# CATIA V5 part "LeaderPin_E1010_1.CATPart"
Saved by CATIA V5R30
Part number: Vodící čep_15-36/95
Nomenclature: E1010/15-36/95
Description: MEUSBURGER
Property "Material": "1.7131"
Publications: "DrillHole", "Base"
Bounding box of the stored display mesh (mm): x -12.298 to 12.298, y -12.297 to 12.297, z 0 to 131
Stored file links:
  E:\Bakalarka\Model\Forma_v7\LeaderPin_E1010_1.CATPart
  E:\dev\MoldDesign\intel_a\startup\components\MoldCatalog\LeaderPin\Meusburger\LeaderPin_E1010\TableE1010.txt
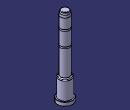
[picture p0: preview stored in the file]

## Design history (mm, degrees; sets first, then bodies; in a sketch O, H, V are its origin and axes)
Parameters
  Ref = "E1010/15-36/95" {design table}
  L1 = 36 mm {design table}
  L2 = 95 mm {design table}
  L3 = 6 mm {design table}
  L4 = 5 mm {design table}
  L5 = 25 mm {design table}
  L6 = 50 mm {design table}
  L7 = 0 mm {design table}
  L8 = 0 mm {design table}
  L11 = 2.4 mm {design table}
  L12 = 10 mm {design table}
  L13 = 2.5 mm {design table}
  D1 = 20 mm {design table}
  D2 = 15 mm {design table}
  D3 = 24.6 mm {design table}
  D4 = 14.6 mm {design table}
  D5 = 14.2 mm {design table}
  R = 1 mm {design table}
  R1 = 15 mm {design table}
  R3 = 1.8 mm {design table}
  R4 = 2 mm {design table}
  R5 = 1 mm {design table}
  F = 0.3 mm {design table}
  W = 15 deg {design table}
  X = 5.5 mm {design table}
  L0 = 131 mm {design table}
  k_d3 = 26 mm {design table}
  k_l3 = 6.3 mm {design table}
  Mat = "1.7131" {design table}
  HeatTreat = "60HRC" {design table}
  SupplierRef = "Meusburger 2017"
  BmpRef = "F_MldLeaderPin_D2_L"
  D = 15 mm {= D2}
  ThL = 36 mm {= L1}
  ThD = 24.6 mm {= D3}
  DrillHole_Length = 225 mm
  L = 95 mm {= L2}
Fillet1: radius 1.8 {= R3}, on edge [face of Shaft1 from Sketch1.L5 | face of Shaft1 from Sketch1.L4]
Set1 "BaseBody"
  Point1 "Base": (0, 0, 0)
  Plane1: type Offset, RefPlane xy-plane, Offset 225 {= DrillHole_Length}, reversed
Body1 "PartBody" (main body)
  Sketch1 on zx-plane, origin (0, 0, 0), H (1, 0, 0), V (0, 0, -1)
    point P1 (0, 0)
    line L1 (0, 0) -> (12.3, 0)
    line L2 (12.3, 0) -> (12.3, -6)
    line L3 (12.3, -6) -> (10, -6)
    point P4 (10, -6)
    point P5 (10, -36)
    line L4 (10, -36) -> (7.5, -36)
    point P6 (7.5, -36)
    point P7 (7.5, -36)
    line L5 (7.5, -36) -> (7.5, -126)
    line L6 (7.5, -126) -> (6.1603, -131)
    line L7 (6.1603, -131) -> (0, -131)
    point P10 (0, -131)
    point P11 (0, -131)
    axis line L8 (0, -131) -> (0, 0)
    point P12 (0, 0)
    point P13 (10, -6)
    line L9 (10, -6) -> (10, -36)
    point P14 (10, -36)
    point P15 (10, -36)
    point P16 (10, -36)
    angle L5 L6 = 15 {= W}
    distance L5 L8 = 7.5 {= D2 /2}
    distance L4 L7 = 95 {= L2}
    distance L2 L8 = 12.3 {= D3 /2}
    length L2 = 6 {= L3}
    distance L1 L4 = 36 {= L1}
    length L6 V = 5 {= L4}
    distance L9 L8 = 10 {= D1 /2}
    coincidence: L8 P10, L8 V, H L1, P1 O, P12 H, P11 L7, P13 P4, P14 P5, L4 P5, L9 P14, P7 P6, P15 P16
    vertical: L2 V, L9 V
    horizontal: L1 H, L4 H, L7 H, L3 H
  Shaft1: profile Sketch1, axis Sketch1.L8, angle 360
  Sketch2 on zx-plane, origin (0, 0, 0), H (-1, 0, 0), V (0, 0, 1)
    arc A1 centre (9.1, 106) radius 2 from (7.5, 107.2) to (7.5, 104.8) ccw
    point P1 (7.1, 106)
    construction line L1 (7.1, 106) -> (11.1, 106)
    point P2 (9.1, 106)
    point P3 (11.1, 106)
    point P4 (-7.1, 106)
    point P5 (-11.1, 106)
    construction line L2 (-7.1, 106) -> (-11.1, 106)
    point P7 (-11.1, 106)
    point P8 (-11.1, 106)
    construction circle A2 centre (-9.1, 106) radius 2
    line L3 (7.5, 107.2) -> (7.5, 104.8)
    radius A1 = 2 {= deleted_LENGTH}
    distance L1 H = 106 {= L1+L2-L5}
    distance P4 P1 = 14.2 {= D5}
    distance L3 V = 7.5 {= D2/2}
    coincidence: P1 A1, P2 L1, P5 A2, P7 P8, P7 P5
    horizontal: L1 H
    symmetry: P1 P4 V, P3 P5 V, L1 L2 V, A1 A2 V
    vertical: L3 V
  Groove1: profile Sketch2, axis Sketch2.V, angle 360
  Sketch3 on zx-plane, origin (0, 0, 0), H (-1, 0, 0), V (0, 0, 1)
    arc A1 centre (9.1, 81) radius 2 from (7.5, 82.2) to (7.5, 79.8) ccw
    point P1 (7.1, 81)
    construction line L1 (7.1, 81) -> (9.1, 81)
    point P2 (9.1, 81)
    point P3 (7.5, 79.8)
    point P4 (7.5, 82.2)
    point P5 (9.1, 81)
    point P6 (-7.1, 81)
    point P7 (-9.1, 81)
    construction line L2 (-7.1, 81) -> (-9.1, 81)
    point P8 (-9.1, 81)
    point P9 (-7.5, 79.8)
    point P10 (-7.5, 82.2)
    construction arc A2 centre (-9.1, 81) radius 2 from (-7.5, 82.2) to (-7.5, 79.8) cw
    line L3 (7.5, 82.2) -> (7.5, 79.8)
    radius A1 = 2 {= deleted_LENGTH}
    distance L1 H = 81 {= L1+L2-L6}
    distance P6 P1 = 14.2 {= D5}
    distance L3 V = 7.5 {= D2/2}
    coincidence: P1 A1, P2 L1, P7 P8
    horizontal: L1 H
    symmetry: P1 P6 V, P5 P7 V, L1 L2 V, P3 P9 V, P4 P10 V, A1 A2 V
    vertical: L3 V
  Groove2: profile Sketch3, axis Sketch3.V, angle 360
  Sketch4 on zx-plane, origin (0, 0, 0), H (-1, 0, 0), V (0, 0, 1)
    arc A1 centre (17.5, 141) radius 2 from (16, 142.3229) to (16, 139.6771) ccw
    point P1 (15.5, 141)
    construction line L1 (15.5, 141) -> (17.5, 141)
    point P2 (17.5, 141)
    point P3 (16, 142.3229)
    point P4 (16, 139.6771)
    point P5 (17.5, 141)
    point P6 (-15.5, 141)
    point P7 (-17.5, 141)
    construction line L2 (-15.5, 141) -> (-17.5, 141)
    point P9 (-16, 142.3229)
    point P10 (-16, 139.6771)
    construction arc A2 centre (-17.5, 141) radius 2 from (-16, 142.3229) to (-16, 139.6771) cw
    line L3 (16, 142.3229) -> (16, 139.6771)
    radius A1 = 2 {= deleted_LENGTH}
    distance L1 H = 131 {= L1+L2-L7}
    distance P6 P1 = 14.2 {= D5}
    distance L3 V = 7.5 {= D2/2}
    coincidence: P1 A1, P2 L1, P5 P2
    horizontal: L1 H
    symmetry: P1 P6 V, P5 P7 V, L1 L2 V, P3 P9 V, P4 P10 V, A1 A2 V
    vertical: L3 V
  Groove3: profile Sketch4, axis Sketch4.V, angle 360, deactivated
  Sketch5 on zx-plane, origin (0, 0, 0), H (-1, 0, 0), V (0, 0, 1)
    arc A1 centre (17.5, 141) radius 2 from (16, 142.3229) to (16, 139.6771) ccw
    point P1 (15.5, 141)
    construction line L1 (15.5, 141) -> (17.5, 141)
    point P2 (17.5, 141)
    point P3 (16, 142.3229)
    point P4 (16, 139.6771)
    point P5 (17.5, 141)
    point P6 (-15.5, 141)
    point P7 (-17.5, 141)
    construction line L2 (-15.5, 141) -> (-17.5, 141)
    point P9 (-16, 142.3229)
    point P10 (-16, 139.6771)
    construction arc A2 centre (-17.5, 141) radius 2 from (-16, 142.3229) to (-16, 139.6771) cw
    line L3 (16, 142.3229) -> (16, 139.6771)
    radius A1 = 2 {= deleted_LENGTH}
    distance L1 H = 131 {= L1+L2-L8}
    distance P6 P1 = 14.2 {= D5}
    distance L3 V = 7.5 {= D2/2}
    coincidence: P1 A1, P2 L1, P5 P2
    horizontal: L1 H
    symmetry: P1 P6 V, P5 P7 V, L1 L2 V, P3 P9 V, P4 P10 V, A1 A2 V
    vertical: L3 V
  Groove4: profile Sketch5, axis Sketch5.V, angle 360, deactivated
  Chamfer1: length 0.3 {= F}, angle 45, on edge [face of Shaft1 from Sketch1.L3 | face of Shaft1 from Sketch1.L2]; edge [face of Shaft1 from Sketch1.L2 | face of Shaft1 from Sketch1.L1]
  Fillet2: radius 15 {= R1}, on edge [face of Shaft1 from Sketch1.L6 | face of Shaft1 from Sketch1.L5]
  Fillet3: radius 1 {= R}, on edge [face of Shaft1 from Sketch1.L7 | face of Shaft1 from Sketch1.L6]
  Fillet4: radius 1, on edge [face of Shaft1 from Sketch1.L4 | face of Shaft1 from Sketch1.L9]
Body2 "DrillHole"
  Sketch6 on Plane1, origin (0, 0, -225), H (1, 0, 0), V (0, 1, 0)
    point P1 (0, 0)
    reference projected point E1 (0, 0) from Point1
    coincidence: E1 P1
  Hole1: placed by Sketch6, at (0, 0, -225) direction (0, 0, 1), diameter 20 {= D1}, depth 356 {= DrillHole_Length +L1+L2}, counterbore diameter 26 {= k_d3}, counterbore depth 231 {= DrillHole_Length +L3}
Relations
  design table "TableE1010", configuration 80, drives Ref, L1, L2, L3, L4, L5, L6, L7, L8, L11, L12, L13, D1, D2, D3, D4, D5, R, R1, R3, R4, R5, F, W, X, L0, k_d3, k_l3, Mat, HeatTreat
  rule "Groove_activity":
    if L5==0mm
    {
    	Groove1.Activity = false
    	Sketch2.Activity = false
    }
    else
    {
    	Groove1.Activity = true
    	Sketch2.Activity = true
    }
    if L6==0mm
    {
    	Groove2.Activity = false
    	Sketch3.Activity = false
    }
    else
    {
    	Groove2.Activity = true
    	Sketch3.Activity = true
    }
    if L7==0mm
    {
    	Groove3.Activity = false
    	Sketch4.Activity = false
    }
    else
    {
    	Groove3.Activity = true
    	Sketch4.Activity = true
    }
    if L8==0mm
    {
    	Groove4.Activity = false
    	Sketch5.Activity = false
    }
    else
    {
    	Groove4.Activity = true
    	Sketch5.Activity = true
    }
  rule "Radius_Rule":
    If R5 == 0mm
    {
    	Fillet4.Radius  = 0.1mm
    	Fillet4.Activity  = false
    }
    else
    {
    	Fillet4.Radius  = R5
    	Fillet4.Activity  = true
    }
